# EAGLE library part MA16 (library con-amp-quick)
AMP QUICK CONNECTOR
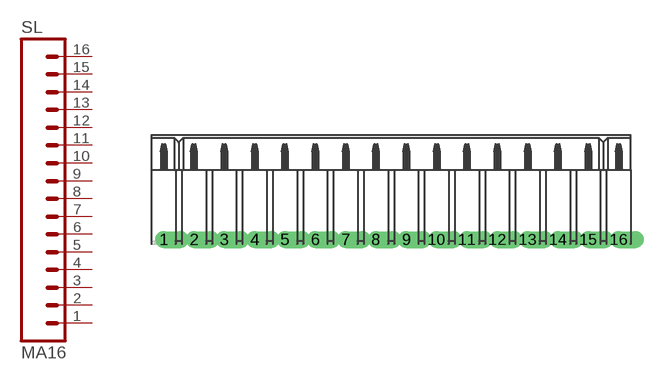
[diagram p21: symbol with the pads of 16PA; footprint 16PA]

Designator prefix SL

## MA16  [16PA]
1  1  pas
2  2  pas
3  3  pas
4  4  pas
5  5  pas
6  6  pas
7  7  pas
8  8  pas
9  9  pas
10  10  pas
11  11  pas
12  12  pas
13  13  pas
14  14  pas
15  15  pas
16  16  pas

## Footprint 16PA (pad centres in mm)
AMP QUICK CONNECTOR
drill 0.914 offset: 1 -19.05,0; 2 -16.51,0; 3 -13.97,0; 4 -11.43,0; 5 -8.89,0; 6 -6.35,0; 7 -3.81,0; 8 -1.27,0; 9 1.27,0; 10 3.81,0; 11 6.35,0; 12 8.89,0; 13 11.43,0; 14 13.97,0; 15 16.51,0; 16 19.05,0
